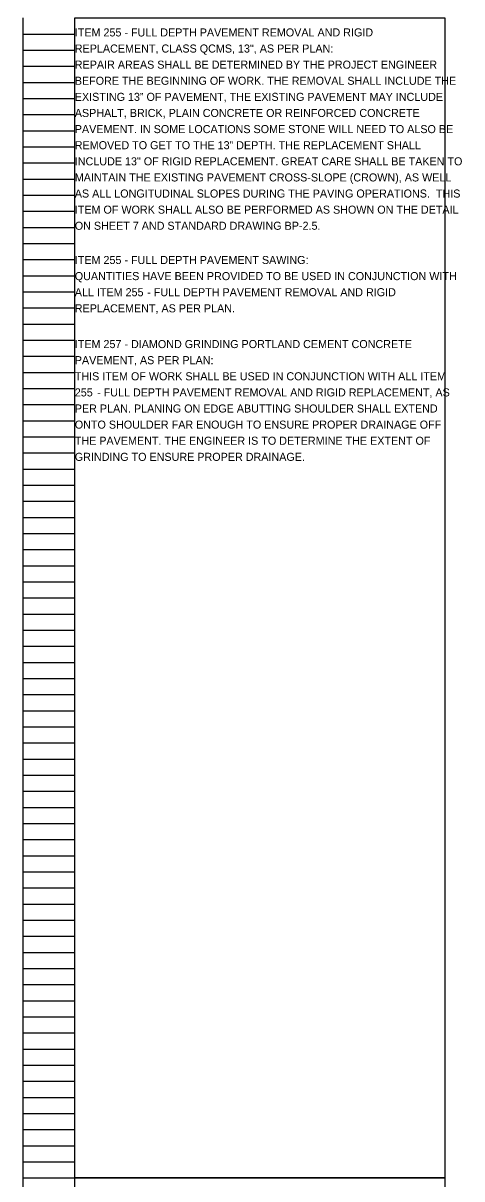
# Model space of a CAD drawing. Extents: x 16463 to 16495, y 5662 to 5823.
# Drawn here: x 16463.05 to 16470.69, y 5762.98 to 5783.06 of the extents above; entities that cross this region are included whole.
import ezdxf

# ---------------------------------------------------------------- set-up
doc = ezdxf.new("R2010")
doc.units = 0
for name, color, linetype in [('Default', 7, 'Continuous'), ('SC_Scratch1', 7, 'Continuous'), ('SH_Data', 7, 'Continuous')]:
    doc.layers.add(name, color=color, linetype=linetype)

msp = doc.modelspace()

# ---------------------------------------------------------------- linework, layer by layer
at = {"layer": 'SC_Scratch1'}
for points in [[(16463.949, 5783.152), (16470.389, 5783.152), (16470.389, 5762.992), (16463.949, 5762.992)], [(16463.949, 5762.992), (16470.389, 5762.992), (16470.389, 5742.832), (16463.949, 5742.832)]]:
    msp.add_lwpolyline(points, close=True, dxfattribs=at)
at = {"layer": 'SH_Data'}
for p, q in [((16463.049, 5762.992), (16463.049, 5783.152)), ((16463.949, 5762.992), (16463.949, 5783.152)), ((16463.049, 5782.872), (16463.949, 5782.872)), ((16463.049, 5782.592), (16463.949, 5782.592)), ((16463.049, 5782.312), (16463.949, 5782.312)), ((16463.049, 5782.032), (16463.949, 5782.032)), ((16463.049, 5781.752), (16463.949, 5781.752)), ((16463.049, 5781.472), (16463.949, 5781.472)), ((16463.049, 5781.192), (16463.949, 5781.192)), ((16463.049, 5780.912), (16463.949, 5780.912)), ((16463.049, 5780.632), (16463.949, 5780.632)), ((16463.049, 5780.352), (16463.949, 5780.352)), ((16463.049, 5780.072), (16463.949, 5780.072)), ((16463.049, 5779.792), (16463.949, 5779.792)), ((16463.049, 5779.512), (16463.949, 5779.512)), ((16463.049, 5779.232), (16463.949, 5779.232)), ((16463.049, 5778.952), (16463.949, 5778.952)), ((16463.049, 5778.672), (16463.949, 5778.672)), ((16463.049, 5778.392), (16463.949, 5778.392)), ((16463.049, 5778.112), (16463.949, 5778.112)), ((16463.049, 5777.832), (16463.949, 5777.832)), ((16463.049, 5777.552), (16463.949, 5777.552)), ((16463.049, 5777.272), (16463.949, 5777.272)), ((16463.049, 5776.992), (16463.949, 5776.992)), ((16463.049, 5776.712), (16463.949, 5776.712)), ((16463.049, 5776.432), (16463.949, 5776.432)), ((16463.049, 5776.152), (16463.949, 5776.152)), ((16463.049, 5775.872), (16463.949, 5775.872)), ((16463.049, 5775.592), (16463.949, 5775.592)), ((16463.049, 5775.312), (16463.949, 5775.312)), ((16463.049, 5775.032), (16463.949, 5775.032)), ((16463.049, 5774.752), (16463.949, 5774.752)), ((16463.049, 5774.472), (16463.949, 5774.472)), ((16463.049, 5774.192), (16463.949, 5774.192)), ((16463.049, 5773.912), (16463.949, 5773.912)), ((16463.049, 5773.632), (16463.949, 5773.632)), ((16463.049, 5773.352), (16463.949, 5773.352)), ((16463.049, 5773.072), (16463.949, 5773.072)), ((16463.049, 5772.792), (16463.949, 5772.792)), ((16463.049, 5772.512), (16463.949, 5772.512)), ((16463.049, 5772.232), (16463.949, 5772.232)), ((16463.049, 5771.952), (16463.949, 5771.952)), ((16463.049, 5771.672), (16463.949, 5771.672)), ((16463.049, 5771.392), (16463.949, 5771.392)), ((16463.049, 5771.112), (16463.949, 5771.112)), ((16463.049, 5770.832), (16463.949, 5770.832)), ((16463.049, 5770.552), (16463.949, 5770.552)), ((16463.049, 5770.272), (16463.949, 5770.272)), ((16463.049, 5769.992), (16463.949, 5769.992)), ((16463.049, 5769.712), (16463.949, 5769.712)), ((16463.049, 5769.432), (16463.949, 5769.432)), ((16463.049, 5769.152), (16463.949, 5769.152)), ((16463.049, 5768.872), (16463.949, 5768.872)), ((16463.049, 5768.592), (16463.949, 5768.592)), ((16463.049, 5768.312), (16463.949, 5768.312)), ((16463.049, 5768.032), (16463.949, 5768.032)), ((16463.049, 5767.752), (16463.949, 5767.752)), ((16463.049, 5767.472), (16463.949, 5767.472)), ((16463.049, 5767.192), (16463.949, 5767.192)), ((16463.049, 5766.912), (16463.949, 5766.912)), ((16463.049, 5766.632), (16463.949, 5766.632)), ((16463.049, 5766.352), (16463.949, 5766.352)), ((16463.049, 5766.072), (16463.949, 5766.072)), ((16463.049, 5765.792), (16463.949, 5765.792)), ((16463.049, 5765.512), (16463.949, 5765.512)), ((16463.049, 5765.232), (16463.949, 5765.232)), ((16463.049, 5764.952), (16463.949, 5764.952)), ((16463.049, 5764.672), (16463.949, 5764.672)), ((16463.049, 5764.392), (16463.949, 5764.392)), ((16463.049, 5764.112), (16463.949, 5764.112)), ((16463.049, 5763.832), (16463.949, 5763.832)), ((16463.049, 5763.552), (16463.949, 5763.552)), ((16463.049, 5763.272), (16463.949, 5763.272)), ((16463.049, 5742.832), (16463.049, 5762.992)), ((16463.049, 5762.992), (16463.949, 5762.992)), ((16463.049, 5762.992), (16463.949, 5762.992)), ((16463.949, 5742.832), (16463.949, 5762.992))]:
    msp.add_line(p, q, dxfattribs=at)

# ---------------------------------------------------------------- texts
at = {"layer": 'Default'}
for s, p in [('ITEM 255 - FULL DEPTH PAVEMENT REMOVAL AND RIGID ', (16463.949, 5782.831)), ('REPLACEMENT, CLASS QCMS, 13", AS PER PLAN:', (16463.949, 5782.551)), ('REPAIR AREAS SHALL BE DETERMINED BY THE PROJECT ENGINEER ', (16463.949, 5782.271)), ('BEFORE THE BEGINNING OF WORK. THE REMOVAL SHALL INCLUDE THE ', (16463.949, 5781.991)), ('EXISTING 13” OF PAVEMENT, THE EXISTING PAVEMENT MAY INCLUDE ', (16463.949, 5781.711)), ('ASPHALT, BRICK, PLAIN CONCRETE OR REINFORCED CONCRETE ', (16463.949, 5781.431)), ('PAVEMENT. IN SOME LOCATIONS SOME STONE WILL NEED TO ALSO BE ', (16463.949, 5781.151)), ('REMOVED TO GET TO THE 13” DEPTH. THE REPLACEMENT SHALL ', (16463.949, 5780.871)), ('INCLUDE 13" OF RIGID REPLACEMENT. GREAT CARE SHALL BE TAKEN TO ', (16463.949, 5780.591)), ('MAINTAIN THE EXISTING PAVEMENT CROSS-SLOPE (CROWN), AS WELL ', (16463.949, 5780.311)), ('AS ALL LONGITUDINAL SLOPES DURING THE PAVING OPERATIONS.  THIS ', (16463.949, 5780.031)), ('ITEM OF WORK SHALL ALSO BE PERFORMED AS SHOWN ON THE DETAIL ', (16463.949, 5779.751)), ('ON SHEET 7 AND STANDARD DRAWING BP-2.5.', (16463.949, 5779.471)), ('ITEM 255 - FULL DEPTH PAVEMENT SAWING:', (16463.949, 5778.876)), ('QUANTITIES HAVE BEEN PROVIDED TO BE USED IN CONJUNCTION WITH ', (16463.949, 5778.596)), ('ALL ITEM 255', (16463.949, 5778.316)), (' - FULL DEPTH PAVEMENT REMOVAL AND RIGID ', (16465.157, 5778.316)), ('REPLACEMENT, AS PER PLAN. ', (16463.949, 5778.036)), ('ITEM 257 - DIAMOND GRINDING PORTLAND CEMENT CONCRETE ', (16463.949, 5777.415)), ('PAVEMENT, AS PER PLAN:', (16463.949, 5777.135)), ('THIS ITEM OF WORK SHALL BE USED IN CONJUNCTION WITH ALL ITEM ', (16463.949, 5776.855)), ('255', (16463.949, 5776.575)), (' - FULL DEPTH PAVEMENT REMOVAL AND RIGID REPLACEMENT, AS ', (16464.285, 5776.575)), ('PER PLAN. PLANING ON EDGE ABUTTING SHOULDER SHALL EXTEND ', (16463.949, 5776.295)), ('ONTO SHOULDER FAR ENOUGH TO ENSURE PROPER DRAINAGE OFF ', (16463.949, 5776.015)), ('THE PAVEMENT. THE ENGINEER IS TO DETERMINE THE EXTENT OF ', (16463.949, 5775.735)), ('GRINDING TO ENSURE PROPER DRAINAGE.', (16463.949, 5775.455))]:
    msp.add_text(s, height=0.14, dxfattribs=at).set_placement(p)

doc.saveas('drawing.dxf')
